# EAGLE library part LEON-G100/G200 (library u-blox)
LEON-G100/G200 Quad Band GSM/GPRS Voice and Data Modules Source: http://www.u-blox.com
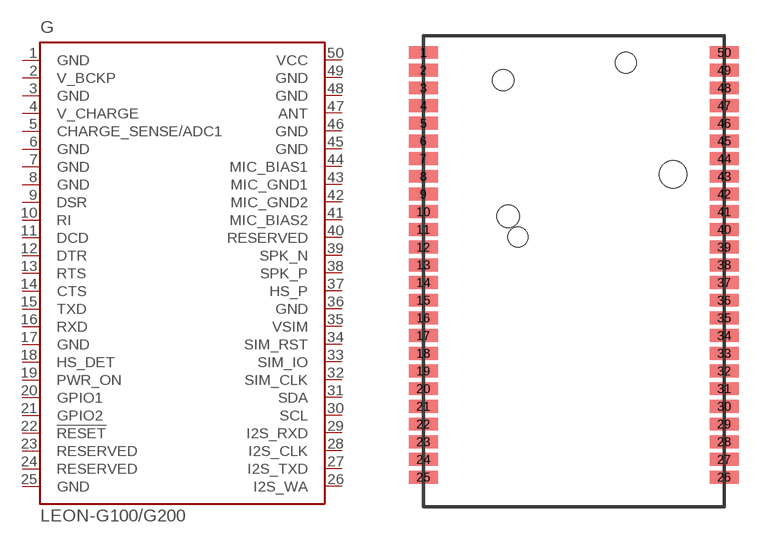
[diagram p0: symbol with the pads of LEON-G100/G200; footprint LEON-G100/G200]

Designator prefix G

## LEON-G100/G200 (OC_FARNELL: unknown; OC_NEWARK: unknown)  [LEON-G100/G200]
1  GND  pwr
2  V_BCKP  in
3  GND  pwr
4  V_CHARGE  in
5  CHARGE_SENSE/ADC1  in
6  GND  pwr
7  GND  pwr
8  GND  pwr
9  DSR  in
10  RI  in
11  DCD  in
12  DTR  in
13  RTS  out
14  CTS  in
15  TXD  out
16  RXD  in
17  GND  pwr
18  HS_DET  in
19  PWR_ON  in
20  GPIO1  in
21  GPIO2  in
22  !RESET  in
23  RESERVED  pas
24  RESERVED  pas
25  GND  pwr
26  I2S_WA  out
27  I2S_TXD  out
28  I2S_CLK  out
29  I2S_RXD  out
30  SCL  in
31  SDA  in
32  SIM_CLK  in
33  SIM_IO  in
34  SIM_RST  in
35  VSIM  in
36  GND  pwr
37  HS_P  out
38  SPK_P  out
39  SPK_N  out
40  RESERVED  pas
41  MIC_BIAS2  in
42  MIC_GND2  pas
43  MIC_GND1  pas
44  MIC_BIAS1  in
45  GND  pwr
46  GND  pwr
47  ANT
48  GND  pwr
49  GND  pwr
50  VCC  pwr

## Footprint LEON-G100/G200 (pad centres in mm)
LEON-G100/G200 Quad Band GSM/GPRS Voice and Data Modules Source: http://www.u-blox.com
smd 1.8 x 0.8: 1 -9.35,13.6; 2 -9.35,12.5; 3 -9.35,11.4; 4 -9.35,10.3; 5 -9.35,9.2; 6 -9.35,8.1; 7 -9.35,7; 8 -9.35,5.9; 9 -9.35,4.8; 10 -9.35,3.7; 11 -9.35,2.6; 12 -9.35,1.5; 13 -9.35,0.4; 14 -9.35,-0.7; 15 -9.35,-1.8; 16 -9.35,-2.9; 17 -9.35,-4; 18 -9.35,-5.1; 19 -9.35,-6.2; 20 -9.35,-7.3; 21 -9.35,-8.4; 22 -9.35,-9.5; 23 -9.35,-10.6; 24 -9.35,-11.7; 25 -9.35,-12.8; 26 9.35,-12.8; 27 9.35,-11.7; 28 9.35,-10.6; 29 9.35,-9.5; 30 9.35,-8.4; 31 9.35,-7.3; 32 9.35,-6.2; 33 9.35,-5.1; 34 9.35,-4; 35 9.35,-2.9; 36 9.35,-1.8; 37 9.35,-0.7; 38 9.35,0.4; 39 9.35,1.5; 40 9.35,2.6; 41 9.35,3.7; 42 9.35,4.8; 43 9.35,5.9; 44 9.35,7; 45 9.35,8.1; 46 9.35,9.2; 47 9.35,10.3; 48 9.35,11.4; 49 9.35,12.5; 50 9.35,13.6
hole 1.31 at -4.39,11.88
hole 1.29 at 3.23,12.96
hole 1.7 at 6.16,6.02
hole 1.4 at -4.07,3.42
hole 1.24 at -3.47,2.12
